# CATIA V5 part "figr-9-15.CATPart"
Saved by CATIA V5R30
Part number: Part1
Bounding box of the stored display mesh (mm): x -77.304 to 77.304, y -77.304 to 118.168, z 0 to 125
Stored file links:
  D:\PROJECTS\CATIA V56R 2020\Resources\Parts File\c09_catia_v5_6r2020_prt\figr-9-15.CATPart
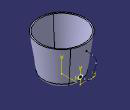
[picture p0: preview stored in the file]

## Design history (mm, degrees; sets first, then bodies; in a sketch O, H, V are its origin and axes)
Set1
  Plane1: type Normal, Curve Sketch3, RefPoint vertex of Sketch3
Body1 (main body)
  Sketch1 on yz-plane, origin (0, 0, 0), H (0, 1, 0), V (0, 0, 1)
    line L1 (0, 0) -> (60, 0)
    point P1 (60, 0)
    point P2 (60, 0)
    line L2 (60, 0) -> (77.5, 125)
    point P3 (77.5, 125)
    line L3 (77.5, 125) -> (0, 125)
    point P4 (0, 125)
    line L4 (0, 125) -> (0, 0)
    axis line L5 (0, 150.2858) -> (0, -31.0593)
    point P5 (0, 150.2858)
    radius about axis P1 L5 = 60
    radius about axis P3 L5 = 77.5
    distance L3 L1 = 125
    horizontal: L1 H, L3 H
    coincidence: P4 V, P2 P1, P5 V
    vertical: L4 V, L5 V
  Shaft1: profile Sketch1, axis Sketch1.L5, angle 360
  Fillet1: radius 15, on edge [face of Shaft1 | face of Shaft1]
  Shell1: ExtOffset 0, Face face of Shaft1, IntOffset 4
  Sketch2 on Plane1, origin (0, 62.9841, 0), H (-1, 0, 0), V (0, 0, 1)
    circle A1 centre (0, 22.002) radius 7.5
    reference projected point E1 (0, 22.002) from vertex of Sketch3
    radius A1 = 7.5
    concentricity: A1 E1
  Sketch3 on yz-plane, origin (0, 0, 0), H (0, 1, 0), V (0, 0, 1)
    line L1 (62.9841, 22.002) -> (78.2172, 22.002)
    arc A1 centre (78.2172, 44.1133) radius 22.1113 from (78.2172, 22.002) to (97.9307, 34.0988) ccw
    arc A2 centre (-112.3295, 140.9107) radius 235.8349 from (97.9307, 34.0988) to (117.8681, 89.6549) ccw
    arc A3 centre (104.0328, 92.7355) radius 14.1742 from (117.8681, 89.6549) to (104.4272, 106.9041) ccw
    arc A4 centre (93.6744, -279.4123) radius 386.4661 from (104.4272, 106.9041) to (82.9216, 106.9041) ccw
    horizontal: L1 H
    tangency: A1 L1, A2 A1, A3 A2, A4 A3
